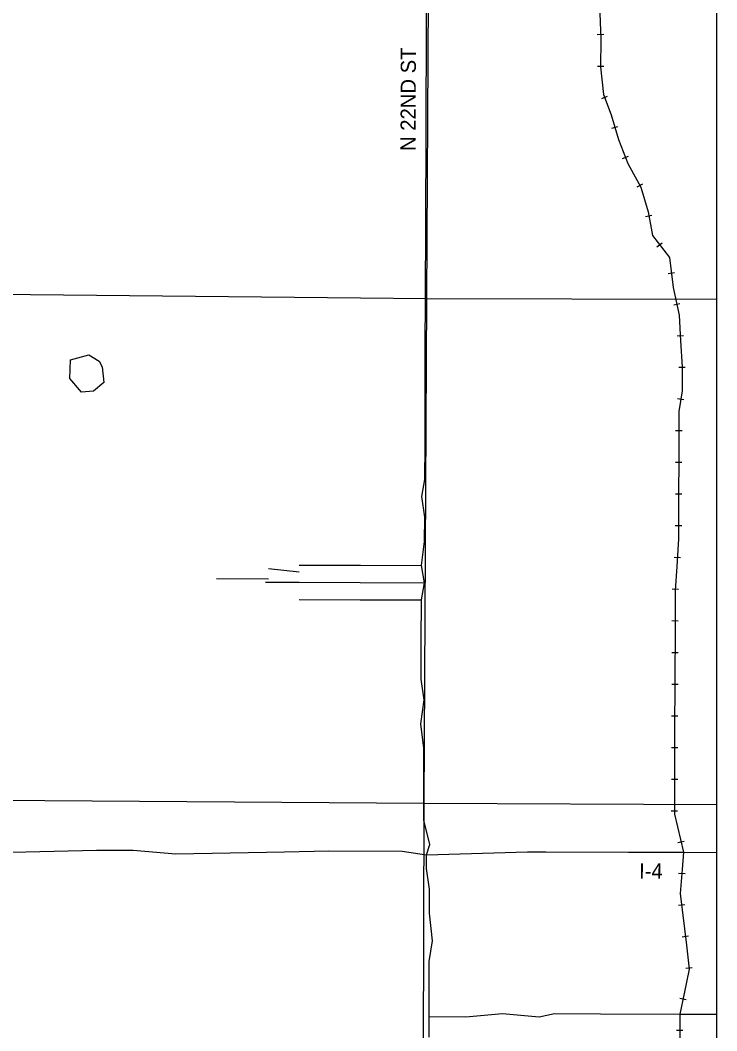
# Model space of a CAD drawing. Extents: x 492225 to 553725, y 1303773 to 1347273.
# Drawn here: x 511586 to 518940, y 1318479 to 1329150 of the extents above; entities that cross this region are included whole.
import ezdxf

# ---------------------------------------------------------------- set-up
doc = ezdxf.new("R2010")
doc.units = 0
for name, color, linetype in [('Level 1', 7, 'Continuous'), ('Level 13', 7, 'Continuous'), ('Level 19', 7, 'Continuous'), ('Level 22', 7, 'Continuous'), ('Level 28', 7, 'Continuous'), ('Level 37', 7, 'Continuous'), ('Level 5', 7, 'Continuous'), ('Level 52', 7, 'Continuous'), ('Level 55', 7, 'Continuous')]:
    doc.layers.add(name, color=color, linetype=linetype)

msp = doc.modelspace()

# ---------------------------------------------------------------- linework, layer by layer
at = {"layer": 'Level 1'}
for p, q in [((515902.766, 1331568.651), (515873.149, 1326207.263)), ((515873.149, 1326207.263), (510543.414, 1326261.323)), ((515873.149, 1326207.263), (515845.848, 1320879.851)), ((518939.561, 1326201.6785), (515873.149, 1326207.263)), ((515845.848, 1320879.851), (510511.962, 1320917.95)), ((515845.848, 1320879.851), (515834.762, 1315574.291)), ((518939.561, 1320864.7596), (515845.848, 1320879.851))]:
    msp.add_line(p, q, dxfattribs=at)
at = {"layer": 'Level 13'}
for p, q in [((511192.147, 1320356.403), (512389.879, 1320386.567)), ((512389.879, 1320386.567), (512777.243, 1320385.159)), ((512777.243, 1320385.159), (513229.037, 1320347.168)), ((514376.376, 1320368.848), (514843.189, 1320377.72)), ((514843.189, 1320377.72), (515617.919, 1320374.958)), ((515617.919, 1320374.958), (515876.032, 1320337.686)), ((513229.037, 1320347.168), (514376.376, 1320368.848)), ((515876.032, 1320337.686), (516941.414, 1320370.275)), ((516941.414, 1320370.275), (517005.975, 1320370.048)), ((517005.975, 1320370.048), (517135.097, 1320369.594)), ((517135.097, 1320369.594), (518006.667, 1320366.538)), ((518006.667, 1320366.538), (518587.714, 1320364.512)), ((518587.714, 1320364.512), (518939.561, 1320363.2914))]:
    msp.add_line(p, q, dxfattribs=at)
at = {"layer": 'Level 22'}
for p, q in [((515874.417, 1328953.955), (515875.711, 1329317.507)), ((515871.569, 1328154.142), (515874.417, 1328953.955)), ((515870.663, 1327899.656), (515871.569, 1328154.142)), ((515869.757, 1327645.17), (515870.663, 1327899.656)), ((515868.592, 1327317.974), (515869.757, 1327645.17)), ((515867.557, 1327027.133), (515868.592, 1327317.974)), ((515866.909, 1326845.358), (515867.557, 1327027.133)), ((515866.263, 1326663.582), (515866.909, 1326845.358)), ((515865.874, 1326554.516), (515866.263, 1326663.582)), ((515865.099, 1326336.386), (515865.874, 1326554.516)), ((515862.387, 1325574.747), (515865.099, 1326336.386)), ((515861.734, 1325391.153), (515862.251, 1325536.574)), ((515862.251, 1325536.574), (515862.387, 1325574.747)), ((515861.475, 1325318.443), (515861.734, 1325391.153)), ((515860.31, 1324991.248), (515861.475, 1325318.443)), ((515859.145, 1324664.052), (515860.31, 1324991.248)), ((515857.852, 1324300.501), (515859.145, 1324664.052)), ((515824.928, 1324118.839), (515857.852, 1324300.501)), ((515856.429, 1323900.595), (515824.928, 1324118.839)), ((515855.524, 1323646.109), (515856.429, 1323900.595)), ((515822.34, 1323391.738), (515855.524, 1323646.109)), ((515853.971, 1323209.849), (515822.34, 1323391.738)), ((515821.045, 1323028.188), (515853.971, 1323209.849)), ((515820.529, 1322882.768), (515821.045, 1323028.188)), ((515820.01, 1322737.348), (515820.529, 1322882.768)), ((515819.622, 1322628.283), (515820.01, 1322737.348)), ((515818.587, 1322337.442), (515819.622, 1322628.283)), ((515818.069, 1322192.022), (515818.587, 1322337.442)), ((515849.573, 1321973.777), (515818.069, 1322192.022)), ((515816.388, 1321719.406), (515849.573, 1321973.777)), ((515847.762, 1321464.806), (515816.388, 1321719.406)), ((515846.985, 1321246.676), (515847.762, 1321464.806)), ((515846.08, 1320992.191), (515846.985, 1321246.676)), ((515845.046, 1320701.351), (515846.08, 1320992.191)), ((515908.701, 1320446.636), (515845.046, 1320701.351)), ((515876.032, 1320337.686), (515908.701, 1320446.636)), ((515875.515, 1320192.266), (515876.032, 1320337.686)), ((515907.02, 1319974.021), (515875.515, 1320192.266)), ((515906.116, 1319719.536), (515907.02, 1319974.021)), ((515937.362, 1319428.582), (515906.116, 1319719.536)), ((515904.306, 1319210.566), (515937.362, 1319428.582)), ((515903.4, 1318956.081), (515904.306, 1319210.566)), ((515902.238, 1318628.886), (515903.4, 1318956.081)), ((515901.462, 1318410.756), (515902.238, 1318628.886)), ((515902.238, 1318628.886), (516289.619, 1318627.514)), ((516289.619, 1318627.514), (516677.129, 1318662.5)), ((516677.129, 1318662.5), (517064.384, 1318624.781)), ((517064.384, 1318624.781), (517225.92, 1318660.568)), ((517225.92, 1318660.568), (517710.146, 1318658.87)), ((517710.146, 1318658.87), (518549.474, 1318655.94)), ((518549.474, 1318655.94), (518939.561, 1318654.5849))]:
    msp.add_line(p, q, dxfattribs=at)
at = {"layer": 'Level 37'}
for p, q in [((517678.41, 1328998.986), (517745.706, 1329001.459)), ((517679.335, 1328665.523), (517746.677, 1328665.287)), ((517724.499, 1328322.505), (517787.522, 1328346.231)), ((517831.624, 1328008.192), (517896.264, 1328027.073)), ((517943.363, 1327689.703), (518006.079, 1327714.231)), ((518098.64, 1327388.602), (518157.623, 1327421.098)), ((518188.297, 1327077.926), (518254.548, 1327089.997)), ((518308.139, 1326757.704), (518361.464, 1326798.831)), ((518426.51, 1326476.054), (518493.312, 1326484.563)), ((518485.011, 1326143.663), (518550.803, 1326158.025)), ((518521.419, 1325817.154), (518588.656, 1325820.899)), ((518539.629, 1325484.797), (518606.97, 1325484.563)), ((518526.201, 1325155.845), (518592.782, 1325145.757)), ((518505.024, 1324817.578), (518572.365, 1324817.343)), ((518503.854, 1324482.724), (518571.196, 1324482.49)), ((518502.686, 1324147.871), (518570.026, 1324147.637)), ((518501.518, 1323813.018), (518568.858, 1323812.783)), ((518488.964, 1323480.518), (518556.175, 1323476.329)), ((518467.949, 1323146.348), (518535.157, 1323142.108)), ((518465.735, 1322809.524), (518533.077, 1322809.29)), ((518464.567, 1322474.671), (518531.908, 1322474.437)), ((518463.398, 1322139.818), (518530.738, 1322139.583)), ((518462.229, 1321804.964), (518529.569, 1321804.729)), ((518461.06, 1321470.111), (518528.401, 1321469.876)), ((518459.891, 1321135.257), (518527.232, 1321135.023)), ((518458.722, 1320800.403), (518526.064, 1320800.169)), ((518528.948, 1320465.785), (518594.453, 1320481.407)), ((518536.844, 1320145.06), (518603.986, 1320139.885)), ((518534.526, 1319805.137), (518601.405, 1319813.017)), ((518573.705, 1319472.583), (518640.584, 1319480.463)), ((518612.683, 1319140.032), (518679.569, 1319147.857)), ((518549.764, 1318822.788), (518615.697, 1318809.084)), ((518515.204, 1318484.619), (518582.546, 1318484.384))]:
    msp.add_line(p, q, dxfattribs=at)
msp.add_lwpolyline([(517676.588, 1329965.552), (517713.997, 1328947.464), (517712.975, 1328656.623), (517744.228, 1328365.669), (517824.808, 1328151.616), (517901.346, 1327889.588), (517999.869, 1327637.663), (518137.133, 1327388.512), (518213.675, 1327126.483), (518259.276, 1326876.198), (518439.203, 1326642.895), (518479.414, 1326327.189), (518542.949, 1326036.123), (518558.135, 1325763.404), (518573.321, 1325490.685), (518572.433, 1325236.199), (518539.395, 1325018.181), (518538.253, 1324690.986), (518537.491, 1324472.855), (518536.476, 1324182.014), (518535.588, 1323927.529), (518534.699, 1323673.044), (518516.577, 1323382.263), (518500.518, 1323127.831), (518499.629, 1322873.346), (518498.594, 1322577.053), (518497.725, 1322328.02), (518494.807, 1321491.855), (518493.919, 1321237.369), (518493.157, 1321019.239), (518492.269, 1320764.753), (518587.714, 1320364.512), (518573.522, 1320182.784), (518553.911, 1319928.364), (518618.185, 1319382.809), (518647.965, 1319128.218), (518594.783, 1318873.915), (518549.474, 1318655.94), (518548.585, 1318401.455)], dxfattribs=at)
at = {"layer": 'Level 5'}
msp.add_lwpolyline([(512233.856, 1325223.289), (512109.256, 1325365.368), (512118.186, 1325565.339), (512310.025, 1325614.782), (512418.174, 1325547.783), (512451.334, 1325489.353), (512467.495, 1325322.622), (512358.875, 1325231.27), (512233.856, 1325223.289)], close=True, dxfattribs=at)
at = {"layer": 'Level 52'}
msp.add_lwpolyline([(518939.5614, 1342691.8404), (495463.7934, 1342691.8404), (495463.7934, 1307817.676), (518939.5614, 1307817.676)], close=True, dxfattribs=at)
at = {"layer": 'Level 55'}
for p, q in [((514208.312, 1323361.148), (514530.962, 1323323.634)), ((514531.223, 1323396.344), (515176.782, 1323394.036)), ((515176.782, 1323394.036), (515822.34, 1323391.738)), ((513659.193, 1323254.058), (514207.92, 1323252.083)), ((514175.511, 1323215.843), (514530.569, 1323214.568)), ((514530.569, 1323214.568), (515176.131, 1323212.261)), ((515176.131, 1323212.261), (515853.971, 1323209.849)), ((514529.917, 1323032.793), (515175.482, 1323030.485)), ((515175.482, 1323030.485), (515821.045, 1323028.188))]:
    msp.add_line(p, q, dxfattribs=at)

# ---------------------------------------------------------------- texts
at = {"layer": 'Level 19'}
msp.add_text('I-4', height=160, rotation=359.79961949, dxfattribs=at).set_placement((518118.873, 1320086.346))
at = {"layer": 'Level 28'}
msp.add_text('N 22ND ST', height=160, rotation=89.79590836, dxfattribs=at).set_placement((515759.859, 1327768.061))

doc.saveas('drawing.dxf')
